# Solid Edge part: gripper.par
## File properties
Author: nakano
Template: iso metric part.par
Last saved by: nakano
Revision: 6
Application: Solid Edge
Density: 1144.05665420604 kg/m^3
Accuracy: 0.990
Username: nakano
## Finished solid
Body 1: solid body, 640 faces, 1456 edges, 801 vertices.
  Faces by surface: plane 254, cylinder 252, torus 80, sphere 24, spline 18, cone 12
  Edges by curve: line 852, circle 481, spline 46, curve on surface 44, ellipse 29, intersection 4
Bounding box of the edges (mm; curved faces can reach further): 57.074 x 29.743 x 64.364, from (-23.1111, -9.6957, -29.8344) to (33.9627, 20.0477, 34.5292).
Cylindrical faces by radius (mm): R0.0254 x6, R0.0762 x5, R0.2032 x129, R0.635 x24, R0.762 x8, R1.067 x4, R1.27 x4, R1.5 x4, R1.5875 x10, R1.6002 x4, R1.6256 x4, R1.905 x4, R2.413 x2, R2.794 x4, R2.9619 x4, R3.175 x8, R5.08 x4, R5.334 x10, R6.35 x2, R6.5024 x1, R6.985 x2, R8.2804 x4, R11.3284 x2, R11.9426 x1, R14.2252 x2
Conical faces (half-angle, radius in mm at the cone's reference point): 0.5 deg R2.1336 x4, 1 deg R4 x4, 12.0948 deg R1.905 x2, 36.8699 deg R1.524 x1, 36.8699 deg R1.905 x1
Toroidal faces (ring radius, tube radius in mm): R0.9652 r0.635 x4, R1.3597 r0.2032 x2, R1.397 r0.2032 x4, R1.8288 r0.2032 x4, R2.159 r0.635 x4, R2.2821 r0.2032 x4, R2.5908 r0.2032 x2, R2.7587 r0.2032 x4, R2.9718 r0.2032 x8, R3.3782 r0.2032 x3, R3.7006 r0.2032 x4, R4.1864 r0.2032 x4, R4.8768 r0.2032 x1, R5.1308 r0.2032 x6, R5.2832 r0.2032 x2, R5.3086 r0.0254 x2, R5.5372 r0.2032 x4, R5.715 r0.635 x4, R5.969 r0.635 x6, R6.1468 r0.2032 x2, R6.35 r0.635 x2, R10.6934 r0.635 x2, R11.1252 r0.2032 x2
Spherical faces by radius (mm): R0.2032 x16, R0.635 x8
Planar faces by outward normal: +x 18, +y 33, +z 20, -x 22, -y 33, -z 20, oblique 108
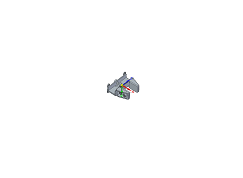
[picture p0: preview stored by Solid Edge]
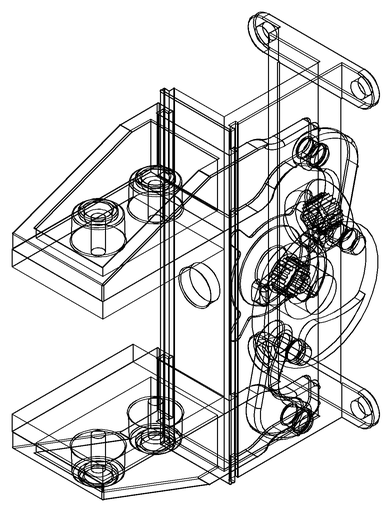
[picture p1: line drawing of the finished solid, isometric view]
